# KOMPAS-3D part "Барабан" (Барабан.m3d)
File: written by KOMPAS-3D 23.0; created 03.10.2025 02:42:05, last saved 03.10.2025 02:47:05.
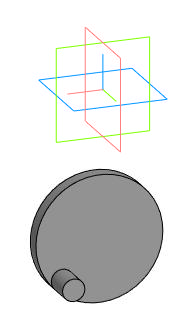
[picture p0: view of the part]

Document properties: Автор: Inspektor_Kot; Полное имя файла: I:\Autodesk Inventor Projects\ИМ-ИТ ЦД\Вариант 13\Барабан.m3d

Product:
- Part/product: Барабан
    Масса: 0.286729

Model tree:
1. Эскиз:1  (with: Элемент выдавливания:3, Элемент выдавливания:5)
2. Элемент выдавливания:1
     Расстояние 1 = 19; Расстояние 2 = 32
3. Эскиз:2  (with: Элемент выдавливания:1)
4. Элемент выдавливания:2  (with: Элемент выдавливания:3)
     Расстояние 1 = -19
5. Эскиз:3  (with: Элемент выдавливания:1, Элемент выдавливания:2)
6. Элемент выдавливания:3
     Расстояние 2 = 8
7. Эскиз:4  (with: Элемент выдавливания:1, Элемент выдавливания:3)
8. Элемент выдавливания:4
     Расстояние 1 = 16
9. Эскиз:5  (with: Элемент выдавливания:1)
10. Элемент выдавливания:5
     Расстояние 2 = 10

Referenced files in I:\Autodesk Inventor Projects\ИМ-ИТ ЦД\Вариант 13\: Стенд ДВС.a3d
